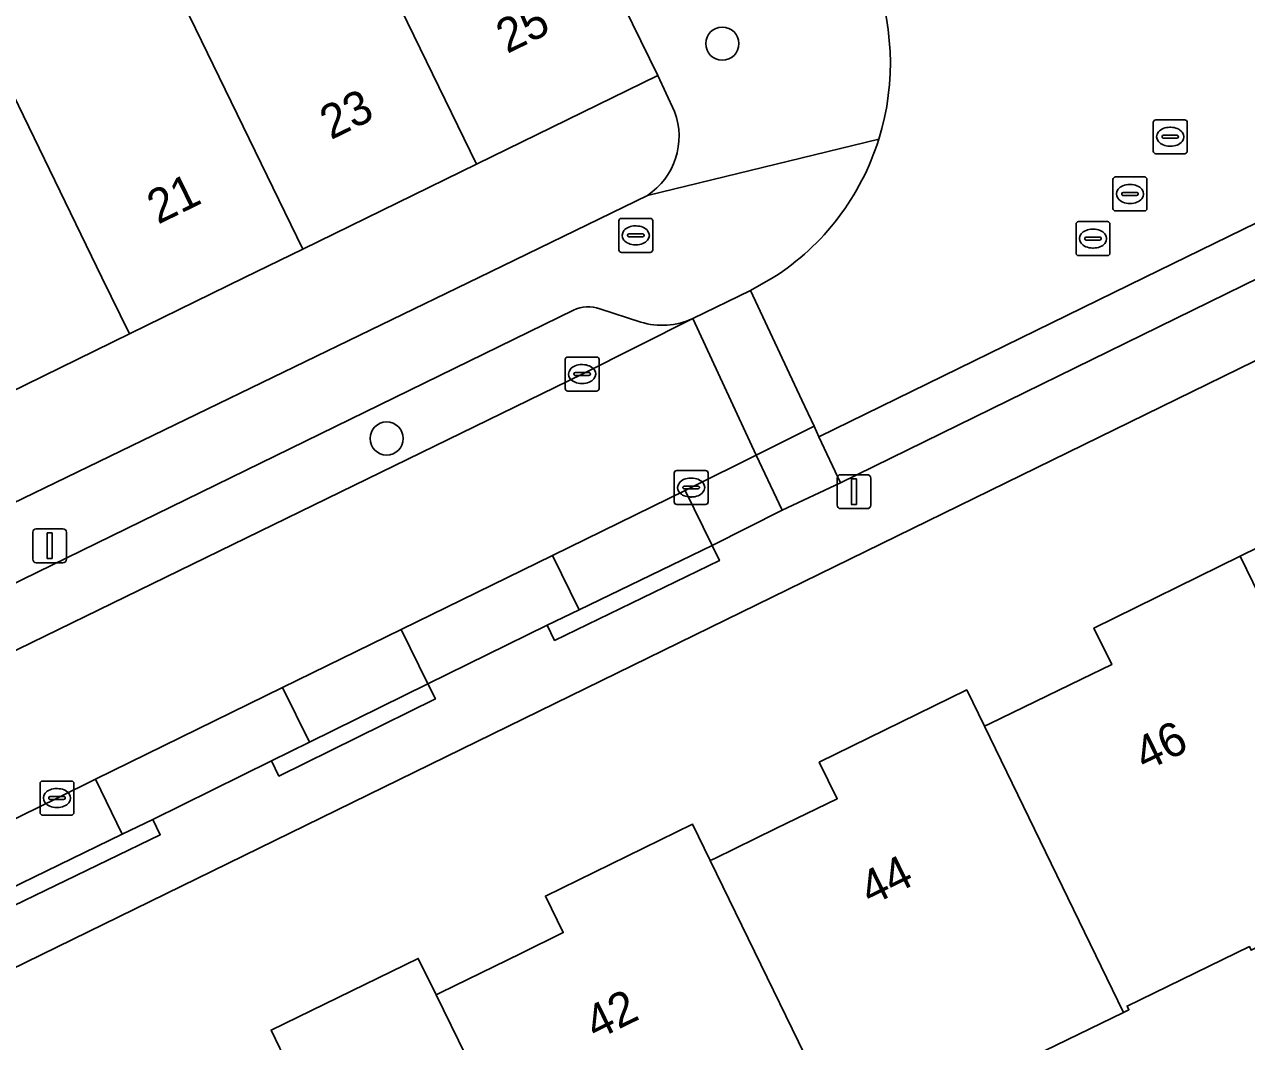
# Model space of a CAD drawing. Extents: x 160455 to 162082, y 388339 to 389736.
# Drawn here: x 160836.74 to 160872.78, y 388727.48 to 388757.47 of the extents above; entities that cross this region are included whole.
import ezdxf

# ---------------------------------------------------------------- set-up
doc = ezdxf.new("R2010")
doc.units = 0
for name, color, linetype in [('IMGEO_Boom', 7, 'Continuous'), ('IMGEO_Brandkraan', 7, 'Continuous'), ('IMGEO_Erf', 7, 'Continuous'), ('IMGEO_Kolk', 7, 'Continuous'), ('IMGEO_Lichtmast', 7, 'Continuous'), ('IMGEO_Pand', 7, 'Continuous'), ('IMGEO_Pand_nummerreeks', 7, 'Continuous'), ('IMGEO_Parkeervlak_open', 7, 'Continuous'), ('IMGEO_Rijbaan_lokaal_gesloten', 7, 'Continuous'), ('IMGEO_Rijbaan_lokaal_open', 7, 'Continuous'), ('IMGEO_Rioolput', 7, 'Continuous'), ('IMGEO_Voetpad_open', 7, 'Continuous')]:
    doc.layers.add(name, color=color, linetype=linetype)

msp = doc.modelspace()

# ---------------------------------------------------------------- linework, layer by layer
at = {"layer": 'IMGEO_Boom'}
for centre in [(160857.324, 388756.9), (160847.424, 388745.255)]:
    msp.add_circle(centre, 0.489, dxfattribs=at)
at = {"layer": 'IMGEO_Brandkraan'}
for p, q in [((160854.272, 388750.82), (160854.272, 388751.672)), ((160854.347, 388751.746), (160855.199, 388751.746)), ((160855.273, 388751.672), (160855.273, 388750.82)), ((160854.531, 388751.24), (160854.531, 388751.252)), ((160854.574, 388751.289), (160854.972, 388751.289)), ((160854.76, 388751.526), (160854.785, 388751.526)), ((160855.015, 388751.252), (160855.015, 388751.24)), ((160854.969, 388751.203), (160854.571, 388751.203)), ((160854.783, 388750.966), (160854.758, 388750.966)), ((160855.199, 388750.746), (160854.347, 388750.746))]:
    msp.add_line(p, q, dxfattribs=at)
for points in [[(160854.272, 388750.82), (160854.272, 388751.672)], [(160854.347, 388751.746), (160855.199, 388751.746)], [(160855.273, 388751.672), (160855.273, 388750.82)], [(160855.199, 388750.746), (160854.347, 388750.746)]]:
    msp.add_lwpolyline(points, dxfattribs=at)
for centre, radius, start, end in [((160854.349, 388751.67), 0.0765, 91.552, 178.448), ((160854.349, 388751.67), 0.0765, 91.552, 178.448), ((160855.197, 388751.67), 0.0765, 1.552, 88.448), ((160855.197, 388751.67), 0.0765, 1.552, 88.448), ((160854.571, 388751.249), 0.0403, 85.8775, 175.7526), ((160854.976, 388751.251), 0.0386, 1.7309, 96.639), ((160854.568, 388751.239), 0.0366, 178.938, 274.7102), ((160854.972, 388751.246), 0.043, 264.8664, 352.4533), ((160854.349, 388750.822), 0.0765, 181.552, 268.448), ((160854.349, 388750.822), 0.0765, 181.552, 268.448), ((160855.197, 388750.822), 0.0765, 271.552, 358.448), ((160855.197, 388750.822), 0.0765, 271.552, 358.448)]:
    msp.add_arc(centre, radius, start, end, dxfattribs=at)
for centre, major_axis, ratio, start_param, end_param in [((160854.759, 388751.246), (-0.387, 0.002), 0.722429, 4.712389, 7.853982), ((160854.784, 388751.246), (-0.39, 0.002), 0.717154, 1.570796, 4.712389)]:
    msp.add_ellipse(centre, major_axis=major_axis, ratio=ratio, start_param=start_param, end_param=end_param, dxfattribs=at)
at = {"layer": 'IMGEO_Erf'}
for points in [[(160796.497, 388787.131), (160798.923, 388782.173), (160800.43, 388779.094), (160801.966, 388775.955), (160804.365, 388771.054), (160807.288, 388772.495), (160811.219, 388764.461), (160808.294, 388763.025), (160809.831, 388759.883), (160812.224, 388754.991), (160810.586, 388754.187), (160812.636, 388750), (160813.015, 388749.225), (160814.601, 388750), (160816.146, 388746.949), (160816.586, 388746.08), (160818.784, 388741.588), (160816.607, 388740.523), (160817.865, 388737.953), (160822.79, 388740.359), (160824.212, 388737.448), (160850.145, 388750), (160855.113, 388752.423)], [(160855.915, 388754.895), (160855.423, 388755.962), (160850.072, 388753.345), (160844.955, 388750.843), (160843.231, 388750), (160839.837, 388748.341), (160834.719, 388745.838)], [(160878.066, 388750), (160811.085, 388717.249)], [(160844.542, 388726.734), (160844.016, 388727.813), (160848.357, 388729.929), (160848.884, 388728.851), (160849.024, 388728.92), (160851.382, 388730.075), (160852.633, 388730.688), (160852.105, 388731.765), (160856.441, 388733.89), (160856.967, 388732.811), (160857.102, 388732.877), (160858.907, 388733.756), (160860.713, 388734.636), (160860.184, 388735.713), (160864.533, 388737.845), (160865.055, 388736.772), (160865.201, 388736.843), (160867.913, 388738.157), (160868.811, 388738.592), (160868.282, 388739.669), (160872.599, 388741.787), (160876.898, 388743.896)], [(160872.867, 388730.274), (160869.261, 388728.52), (160869.313, 388728.412), (160869.159, 388728.337), (160864.835, 388726.234)]]:
    msp.add_lwpolyline(points, dxfattribs=at)
msp.add_arc((160853.966, 388754.161), 2.083, 303.4237, 20.6267, dxfattribs=at)
at = {"layer": 'IMGEO_Kolk'}
for p, q in [((160852.765, 388747.657), (160853.617, 388747.657)), ((160852.69, 388746.731), (160852.69, 388747.583)), ((160853.178, 388747.437), (160853.203, 388747.437)), ((160853.691, 388747.583), (160853.691, 388746.731)), ((160852.949, 388747.151), (160852.949, 388747.163)), ((160853.387, 388747.114), (160852.989, 388747.114)), ((160852.992, 388747.2), (160853.39, 388747.2)), ((160853.433, 388747.163), (160853.433, 388747.151)), ((160853.617, 388746.657), (160852.765, 388746.657)), ((160853.201, 388746.877), (160853.176, 388746.877)), ((160855.904, 388743.386), (160855.904, 388744.238)), ((160855.979, 388744.312), (160856.831, 388744.312)), ((160856.392, 388744.092), (160856.417, 388744.092)), ((160856.905, 388744.238), (160856.905, 388743.386)), ((160856.163, 388743.806), (160856.163, 388743.818)), ((160856.601, 388743.769), (160856.203, 388743.769)), ((160856.206, 388743.855), (160856.604, 388743.855)), ((160856.647, 388743.818), (160856.647, 388743.806)), ((160856.415, 388743.532), (160856.39, 388743.532)), ((160856.831, 388743.312), (160855.979, 388743.312)), ((160837.203, 388734.229), (160837.203, 388735.081)), ((160837.278, 388735.155), (160838.13, 388735.155)), ((160838.204, 388735.081), (160838.204, 388734.229)), ((160837.505, 388734.698), (160837.903, 388734.698)), ((160837.691, 388734.935), (160837.716, 388734.935)), ((160837.462, 388734.649), (160837.462, 388734.661)), ((160837.9, 388734.612), (160837.502, 388734.612)), ((160837.714, 388734.375), (160837.689, 388734.375)), ((160837.946, 388734.661), (160837.946, 388734.649)), ((160838.13, 388734.155), (160837.278, 388734.155))]:
    msp.add_line(p, q, dxfattribs=at)
for points in [[(160852.765, 388747.657), (160853.617, 388747.657)], [(160852.69, 388746.731), (160852.69, 388747.583)], [(160853.691, 388747.583), (160853.691, 388746.731)], [(160853.617, 388746.657), (160852.765, 388746.657)], [(160855.904, 388743.386), (160855.904, 388744.238)], [(160855.979, 388744.312), (160856.831, 388744.312)], [(160856.905, 388744.238), (160856.905, 388743.386)], [(160856.831, 388743.312), (160855.979, 388743.312)], [(160837.203, 388734.229), (160837.203, 388735.081)], [(160837.278, 388735.155), (160838.13, 388735.155)], [(160838.204, 388735.081), (160838.204, 388734.229)], [(160838.13, 388734.155), (160837.278, 388734.155)]]:
    msp.add_lwpolyline(points, dxfattribs=at)
for centre, radius, start, end in [((160852.767, 388747.581), 0.0765, 91.552, 178.448), ((160852.767, 388747.581), 0.0765, 91.552, 178.448), ((160853.615, 388747.581), 0.0765, 1.552, 88.448), ((160853.615, 388747.581), 0.0765, 1.552, 88.448), ((160852.989, 388747.16), 0.0403, 85.8775, 175.7526), ((160852.986, 388747.15), 0.0366, 178.938, 274.7102), ((160853.39, 388747.157), 0.043, 264.8664, 352.4533), ((160853.394, 388747.162), 0.0386, 1.7309, 96.639), ((160852.767, 388746.733), 0.0765, 181.552, 268.448), ((160852.767, 388746.733), 0.0765, 181.552, 268.448), ((160853.615, 388746.733), 0.0765, 271.552, 358.448), ((160853.615, 388746.733), 0.0765, 271.552, 358.448), ((160855.981, 388744.236), 0.0765, 91.552, 178.448), ((160855.981, 388744.236), 0.0765, 91.552, 178.448), ((160856.829, 388744.236), 0.0765, 1.552, 88.448), ((160856.829, 388744.236), 0.0765, 1.552, 88.448), ((160856.203, 388743.815), 0.0403, 85.8775, 175.7526), ((160856.2, 388743.805), 0.0366, 178.938, 274.7102), ((160856.604, 388743.812), 0.043, 264.8664, 352.4533), ((160856.608, 388743.817), 0.0386, 1.7309, 96.639), ((160855.981, 388743.388), 0.0765, 181.552, 268.448), ((160855.981, 388743.388), 0.0765, 181.552, 268.448), ((160856.829, 388743.388), 0.0765, 271.552, 358.448), ((160856.829, 388743.388), 0.0765, 271.552, 358.448), ((160837.28, 388735.079), 0.0765, 91.552, 178.448), ((160837.28, 388735.079), 0.0765, 91.552, 178.448), ((160838.128, 388735.079), 0.0765, 1.552, 88.448), ((160838.128, 388735.079), 0.0765, 1.552, 88.448), ((160837.502, 388734.658), 0.0403, 85.8775, 175.7526), ((160837.907, 388734.66), 0.0386, 1.7309, 96.639), ((160837.499, 388734.648), 0.0366, 178.938, 274.7102), ((160837.903, 388734.655), 0.043, 264.8664, 352.4533), ((160837.28, 388734.231), 0.0765, 181.552, 268.448), ((160837.28, 388734.231), 0.0765, 181.552, 268.448), ((160838.128, 388734.231), 0.0765, 271.552, 358.448), ((160838.128, 388734.231), 0.0765, 271.552, 358.448)]:
    msp.add_arc(centre, radius, start, end, dxfattribs=at)
for centre, major_axis, ratio, start_param, end_param in [((160853.177, 388747.157), (-0.387, 0.002), 0.722429, 4.712389, 7.853982), ((160853.202, 388747.157), (-0.39, 0.002), 0.717154, 1.570796, 4.712389), ((160856.391, 388743.812), (-0.387, 0.002), 0.722429, 4.712389, 7.853982), ((160856.416, 388743.812), (-0.39, 0.002), 0.717154, 1.570796, 4.712389), ((160837.69, 388734.655), (-0.387, 0.002), 0.722429, 4.712389, 7.853982), ((160837.715, 388734.655), (-0.39, 0.002), 0.717154, 1.570796, 4.712389)]:
    msp.add_ellipse(centre, major_axis=major_axis, ratio=ratio, start_param=start_param, end_param=end_param, dxfattribs=at)
at = {"layer": 'IMGEO_Lichtmast'}
for p, q in [((160860.711, 388743.289), (160860.711, 388744.089)), ((160860.711, 388744.089), (160860.711, 388743.289)), ((160860.811, 388744.189), (160861.601, 388744.189)), ((160861.601, 388744.189), (160860.811, 388744.189)), ((160861.701, 388744.089), (160861.701, 388743.289)), ((160861.701, 388743.289), (160861.701, 388744.089)), ((160861.601, 388743.189), (160860.811, 388743.189)), ((160860.811, 388743.189), (160861.601, 388743.189)), ((160837.09, 388742.596), (160837.88, 388742.596)), ((160837.88, 388742.596), (160837.09, 388742.596)), ((160836.99, 388741.696), (160836.99, 388742.496)), ((160836.99, 388742.496), (160836.99, 388741.696)), ((160837.98, 388742.496), (160837.98, 388741.696)), ((160837.98, 388741.696), (160837.98, 388742.496)), ((160837.88, 388741.596), (160837.09, 388741.596)), ((160837.09, 388741.596), (160837.88, 388741.596))]:
    msp.add_line(p, q, dxfattribs=at)
for points in [[(160861.131, 388744.064), (160861.281, 388744.064), (160861.281, 388743.314), (160861.131, 388743.314), (160861.131, 388744.064)], [(160837.41, 388742.471), (160837.56, 388742.471), (160837.56, 388741.721), (160837.41, 388741.721), (160837.41, 388742.471)]]:
    msp.add_lwpolyline(points, dxfattribs=at)
for centre, start, end in [((160860.811, 388744.089), 90, 180), ((160860.811, 388744.089), 90, 180), ((160861.601, 388744.089), 0, 90), ((160861.601, 388744.089), 360, 90), ((160860.811, 388743.289), 180, 270), ((160860.811, 388743.289), 180, 270), ((160861.601, 388743.289), 270, 0), ((160861.601, 388743.289), 270, 0), ((160837.09, 388742.496), 90, 180), ((160837.09, 388742.496), 90, 180), ((160837.88, 388742.496), 0, 90), ((160837.88, 388742.496), 360, 90), ((160837.09, 388741.696), 180, 270), ((160837.09, 388741.696), 180, 270), ((160837.88, 388741.696), 270, 0), ((160837.88, 388741.696), 270, 0)]:
    msp.add_arc(centre, 0.1, start, end, dxfattribs=at)
at = {"layer": 'IMGEO_Pand'}
for points in [[(160850.954, 388765.091), (160847.781, 388762.217), (160847.24, 388761.727), (160846.552, 388761.105), (160846.377, 388760.947), (160850.072, 388753.345), (160855.423, 388755.962)], [(160846.377, 388760.947), (160845.71, 388762.319), (160843.124, 388760.07), (160841.435, 388758.601), (160841.258, 388758.447), (160844.955, 388750.843), (160850.072, 388753.345)], [(160841.258, 388758.447), (160840.593, 388759.815), (160838.235, 388757.784), (160836.927, 388760.605), (160834.969, 388758.854), (160835.65, 388757.462), (160835.476, 388757.311), (160839.03, 388750), (160839.837, 388748.341), (160843.231, 388750), (160844.955, 388750.843)], [(160835.476, 388757.311), (160832.962, 388755.124), (160831.201, 388753.592), (160831.024, 388753.438), (160832.696, 388750), (160834.719, 388745.838), (160839.837, 388748.341), (160839.03, 388750)], [(160881.194, 388744.662), (160881.029, 388744.581), (160879.228, 388743.7), (160877.427, 388742.819), (160876.898, 388743.896), (160872.599, 388741.787), (160877.233, 388732.263), (160881.562, 388734.368), (160881.509, 388734.476), (160885.115, 388736.23), (160885.168, 388736.122), (160885.316, 388736.194)], [(160872.599, 388741.787), (160868.282, 388739.669), (160868.811, 388738.592), (160867.913, 388738.157), (160865.201, 388736.843), (160865.055, 388736.772), (160869.159, 388728.337), (160869.313, 388728.412), (160869.261, 388728.52), (160872.867, 388730.274), (160872.919, 388730.166), (160877.233, 388732.263)], [(160865.055, 388736.772), (160864.533, 388737.845), (160860.184, 388735.713), (160860.713, 388734.636), (160858.907, 388733.756), (160857.102, 388732.877), (160856.967, 388732.811), (160861.066, 388724.401), (160861.22, 388724.476), (160861.167, 388724.584), (160864.782, 388726.342), (160864.835, 388726.234), (160869.159, 388728.337)], [(160856.967, 388732.811), (160856.441, 388733.89), (160852.105, 388731.765), (160852.633, 388730.688), (160851.382, 388730.075), (160849.024, 388728.92), (160848.884, 388728.851), (160853.04, 388720.353), (160853.193, 388720.428), (160853.14, 388720.536), (160856.741, 388722.298), (160861.066, 388724.401)], [(160848.884, 388728.851), (160848.357, 388729.929), (160844.016, 388727.813), (160844.542, 388726.734), (160843.1, 388726.028), (160842.199, 388725.586), (160840.938, 388724.968), (160840.791, 388724.896), (160844.958, 388716.398), (160845.111, 388716.473), (160845.058, 388716.581), (160848.668, 388718.347), (160848.721, 388718.239), (160853.04, 388720.353)]]:
    msp.add_lwpolyline(points, close=True, dxfattribs=at)
at = {"layer": 'IMGEO_Parkeervlak_open'}
for points in [[(160860.175, 388745.303), (160860.806, 388743.953), (160873.165, 388750), (160879.107, 388752.907), (160878.433, 388754.232), (160869.779, 388750)], [(160858.322, 388744.767), (160859.088, 388743.145), (160860.806, 388743.953), (160860.175, 388745.303), (160860.028, 388745.616)], [(160858.322, 388744.767), (160856.405, 388743.813), (160856.229, 388743.727), (160857.023, 388742.106), (160859.088, 388743.145)], [(160857.023, 388742.106), (160856.229, 388743.727), (160852.314, 388741.81), (160853.099, 388740.207)], [(160853.099, 388740.207), (160852.314, 388741.81), (160847.856, 388739.627), (160848.64, 388738.026), (160852.162, 388739.753)], [(160848.64, 388738.026), (160847.856, 388739.627), (160844.357, 388737.914), (160845.146, 388736.302)], [(160845.146, 388736.302), (160844.357, 388737.914), (160838.835, 388735.21), (160839.629, 388733.589), (160840.529, 388734.025), (160844.025, 388735.749)], [(160838.835, 388735.21), (160837.704, 388734.656), (160835.109, 388733.382), (160835.895, 388731.782), (160839.629, 388733.589)]]:
    msp.add_lwpolyline(points, close=True, dxfattribs=at)
for points in [[(160854.918, 388748.69), (160853.711, 388749.081)], [(160814.348, 388728.165), (160817.647, 388729.787), (160836.158, 388738.845), (160853.191, 388747.155), (160856.45, 388748.792)], [(160852.935, 388749.039), (160816.007, 388730.993)]]:
    msp.add_lwpolyline(points, dxfattribs=at)
for centre, radius, start, end in [((160853.37, 388748.194), 0.95, 68.9563, 117.2397), ((160855.549, 388750.767), 2.171, 253.0972, 294.521)]:
    msp.add_arc(centre, radius, start, end, dxfattribs=at)
at = {"layer": 'IMGEO_Rijbaan_lokaal_gesloten'}
msp.add_lwpolyline([(160835.109, 388733.382), (160837.704, 388734.656), (160838.835, 388735.21), (160844.357, 388737.914), (160847.856, 388739.627), (160852.314, 388741.81), (160856.229, 388743.727), (160856.405, 388743.813), (160858.322, 388744.767), (160856.45, 388748.792), (160853.191, 388747.155), (160836.158, 388738.845), (160817.647, 388729.787), (160814.348, 388728.165), (160810.77, 388726.43)], dxfattribs=at)
at = {"layer": 'IMGEO_Rijbaan_lokaal_open'}
msp.add_lwpolyline([(160858.828, 388750), (160858.158, 388749.617), (160859.667, 388746.388), (160860.028, 388745.616), (160860.175, 388745.303), (160869.779, 388750), (160878.433, 388754.232)], dxfattribs=at)
msp.add_lwpolyline([(160858.322, 388744.767), (160860.028, 388745.616), (160859.667, 388746.388), (160858.158, 388749.617), (160856.45, 388748.792)], close=True, dxfattribs=at)
for centre, radius, start, end in [((160854.771, 388756.32), 7.509, 342.6866, 22.6715), ((160854.772, 388756.318), 7.508, 302.701, 342.6979)]:
    msp.add_arc(centre, radius, start, end, dxfattribs=at)
at = {"layer": 'IMGEO_Rioolput'}
for p, q in [((160870.033, 388753.728), (160870.033, 388754.58)), ((160870.108, 388754.654), (160870.96, 388754.654)), ((160871.034, 388754.58), (160871.034, 388753.728)), ((160870.292, 388754.148), (160870.292, 388754.16)), ((160870.335, 388754.197), (160870.733, 388754.197)), ((160870.521, 388754.434), (160870.546, 388754.434)), ((160870.776, 388754.16), (160870.776, 388754.148)), ((160870.73, 388754.111), (160870.332, 388754.111)), ((160870.544, 388753.874), (160870.519, 388753.874)), ((160870.96, 388753.654), (160870.108, 388753.654)), ((160868.845, 388752.042), (160868.845, 388752.894)), ((160868.92, 388752.968), (160869.772, 388752.968)), ((160869.333, 388752.748), (160869.358, 388752.748)), ((160869.846, 388752.894), (160869.846, 388752.042)), ((160869.104, 388752.462), (160869.104, 388752.474)), ((160869.542, 388752.425), (160869.144, 388752.425)), ((160869.147, 388752.511), (160869.545, 388752.511)), ((160869.588, 388752.474), (160869.588, 388752.462)), ((160869.772, 388751.968), (160868.92, 388751.968)), ((160869.356, 388752.188), (160869.331, 388752.188)), ((160867.83, 388751.652), (160868.682, 388751.652)), ((160867.755, 388750.726), (160867.755, 388751.578)), ((160868.243, 388751.432), (160868.268, 388751.432)), ((160868.756, 388751.578), (160868.756, 388750.726)), ((160868.014, 388751.146), (160868.014, 388751.158)), ((160868.452, 388751.109), (160868.054, 388751.109)), ((160868.057, 388751.195), (160868.455, 388751.195)), ((160868.498, 388751.158), (160868.498, 388751.146)), ((160868.682, 388750.652), (160867.83, 388750.652)), ((160868.266, 388750.872), (160868.241, 388750.872))]:
    msp.add_line(p, q, dxfattribs=at)
for points in [[(160870.033, 388753.728), (160870.033, 388754.58)], [(160870.108, 388754.654), (160870.96, 388754.654)], [(160871.034, 388754.58), (160871.034, 388753.728)], [(160870.96, 388753.654), (160870.108, 388753.654)], [(160868.845, 388752.042), (160868.845, 388752.894)], [(160868.92, 388752.968), (160869.772, 388752.968)], [(160869.846, 388752.894), (160869.846, 388752.042)], [(160869.772, 388751.968), (160868.92, 388751.968)], [(160867.83, 388751.652), (160868.682, 388751.652)], [(160867.755, 388750.726), (160867.755, 388751.578)], [(160868.756, 388751.578), (160868.756, 388750.726)], [(160868.682, 388750.652), (160867.83, 388750.652)]]:
    msp.add_lwpolyline(points, dxfattribs=at)
for centre, radius, start, end in [((160870.11, 388754.578), 0.0765, 91.552, 178.448), ((160870.11, 388754.578), 0.0765, 91.552, 178.448), ((160870.958, 388754.578), 0.0765, 1.552, 88.448), ((160870.958, 388754.578), 0.0765, 1.552, 88.448), ((160870.332, 388754.157), 0.0403, 85.8775, 175.7526), ((160870.329, 388754.147), 0.0366, 178.938, 274.7102), ((160870.733, 388754.154), 0.043, 264.8664, 352.4533), ((160870.737, 388754.159), 0.0386, 1.7309, 96.639), ((160870.11, 388753.73), 0.0765, 181.552, 268.448), ((160870.11, 388753.73), 0.0765, 181.552, 268.448), ((160870.958, 388753.73), 0.0765, 271.552, 358.448), ((160870.958, 388753.73), 0.0765, 271.552, 358.448), ((160868.922, 388752.892), 0.0765, 91.552, 178.448), ((160868.922, 388752.892), 0.0765, 91.552, 178.448), ((160869.77, 388752.892), 0.0765, 1.552, 88.448), ((160869.77, 388752.892), 0.0765, 1.552, 88.448), ((160869.144, 388752.471), 0.0403, 85.8775, 175.7526), ((160869.141, 388752.461), 0.0366, 178.938, 274.7102), ((160869.545, 388752.468), 0.043, 264.8664, 352.4533), ((160869.549, 388752.473), 0.0386, 1.7309, 96.639), ((160868.922, 388752.044), 0.0765, 181.552, 268.448), ((160868.922, 388752.044), 0.0765, 181.552, 268.448), ((160869.77, 388752.044), 0.0765, 271.552, 358.448), ((160869.77, 388752.044), 0.0765, 271.552, 358.448), ((160867.832, 388751.576), 0.0765, 91.552, 178.448), ((160867.832, 388751.576), 0.0765, 91.552, 178.448), ((160868.68, 388751.576), 0.0765, 1.552, 88.448), ((160868.68, 388751.576), 0.0765, 1.552, 88.448), ((160868.054, 388751.155), 0.0403, 85.8775, 175.7526), ((160868.051, 388751.145), 0.0366, 178.938, 274.7102), ((160868.455, 388751.152), 0.043, 264.8664, 352.4533), ((160868.459, 388751.157), 0.0386, 1.7309, 96.639), ((160867.832, 388750.728), 0.0765, 181.552, 268.448), ((160867.832, 388750.728), 0.0765, 181.552, 268.448), ((160868.68, 388750.728), 0.0765, 271.552, 358.448), ((160868.68, 388750.728), 0.0765, 271.552, 358.448)]:
    msp.add_arc(centre, radius, start, end, dxfattribs=at)
for centre, major_axis, ratio, start_param, end_param in [((160870.52, 388754.154), (-0.387, 0.002), 0.722429, 4.712389, 7.853982), ((160870.545, 388754.154), (-0.39, 0.002), 0.717154, 1.570796, 4.712389), ((160869.332, 388752.468), (-0.387, 0.002), 0.722429, 4.712389, 7.853982), ((160869.357, 388752.468), (-0.39, 0.002), 0.717154, 1.570796, 4.712389), ((160868.242, 388751.152), (-0.387, 0.002), 0.722429, 4.712389, 7.853982), ((160868.267, 388751.152), (-0.39, 0.002), 0.717154, 1.570796, 4.712389)]:
    msp.add_ellipse(centre, major_axis=major_axis, ratio=ratio, start_param=start_param, end_param=end_param, dxfattribs=at)
at = {"layer": 'IMGEO_Voetpad_open'}
for points in [[(160839.036, 388786.566), (160828.271, 388808.613), (160827.303, 388810.643), (160820.108, 388820.831), (160842.711, 388774.525), (160845.592, 388775.926), (160850.954, 388765.091), (160855.423, 388755.962), (160855.915, 388754.895)], [(160861.94, 388754.085), (160855.113, 388752.423), (160850.145, 388750), (160824.212, 388737.448), (160811.637, 388731.307), (160808.96, 388729.911)], [(160855.113, 388752.423), (160861.94, 388754.085)], [(160816.666, 388724.342), (160815.673, 388723.851), (160815.893, 388723.403), (160809.661, 388720.335), (160811.085, 388717.249), (160878.066, 388750)], [(160873.165, 388750), (160860.806, 388743.953), (160859.088, 388743.145), (160857.023, 388742.106), (160857.24, 388741.656), (160852.379, 388739.303), (160852.162, 388739.753), (160848.64, 388738.026), (160848.861, 388737.578), (160844.246, 388735.301), (160844.025, 388735.749), (160840.529, 388734.025), (160840.746, 388733.575), (160836.112, 388731.332), (160835.895, 388731.782), (160832.668, 388730.187), (160832.887, 388729.738), (160828.282, 388727.484), (160828.063, 388727.933), (160824.549, 388726.213), (160824.768, 388725.764), (160820.162, 388723.513), (160819.943, 388723.962)], [(160856.45, 388748.792), (160858.158, 388749.617), (160858.828, 388750)], [(160853.711, 388749.081), (160854.918, 388748.69)], [(160816.007, 388730.993), (160852.935, 388749.039)]]:
    msp.add_lwpolyline(points, dxfattribs=at)
for points in [[(160857.24, 388741.656), (160857.023, 388742.106), (160853.099, 388740.207), (160852.162, 388739.753), (160852.379, 388739.303)], [(160848.861, 388737.578), (160848.64, 388738.026), (160845.146, 388736.302), (160844.025, 388735.749), (160844.246, 388735.301)], [(160840.746, 388733.575), (160840.529, 388734.025), (160839.629, 388733.589), (160835.895, 388731.782), (160836.112, 388731.332)]]:
    msp.add_lwpolyline(points, close=True, dxfattribs=at)
for centre, radius, start, end in [((160854.771, 388756.32), 7.509, 342.6866, 22.6715), ((160853.966, 388754.161), 2.083, 303.4237, 20.6267), ((160854.772, 388756.318), 7.508, 302.701, 342.6979), ((160853.37, 388748.194), 0.95, 68.9563, 117.2397), ((160855.549, 388750.767), 2.171, 253.0972, 294.521)]:
    msp.add_arc(centre, radius, start, end, dxfattribs=at)

# ---------------------------------------------------------------- texts
at = {"layer": 'IMGEO_Pand_nummerreeks'}
for s, rotation, p in [('25', 26.0581, (160850.976, 388756.593)), ('23', 26.0581, (160845.779, 388754.051)), ('21', 26.0581, (160840.683, 388751.56)), ('46', 26.0696, (160869.791, 388735.427)), ('44', 26.0696, (160861.693, 388731.466)), ('42', 26.0696, (160853.592, 388727.503))]:
    msp.add_text(s, height=1, rotation=rotation, dxfattribs=at).set_placement(p)

doc.saveas('drawing.dxf')
